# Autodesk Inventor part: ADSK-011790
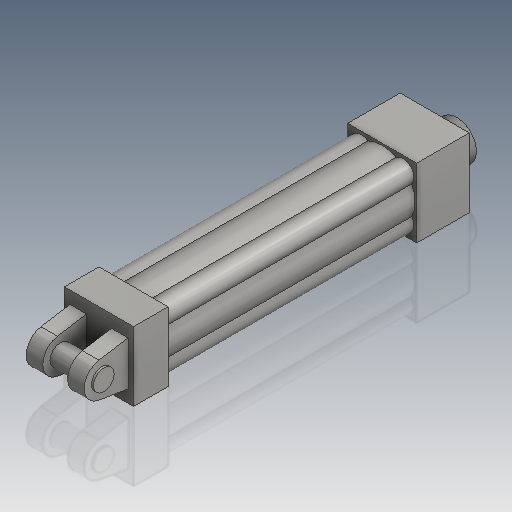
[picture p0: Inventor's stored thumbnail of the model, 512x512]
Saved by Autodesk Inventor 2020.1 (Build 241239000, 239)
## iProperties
Created: 1999-11
Part Number: ADSK-011790
Material: Aluminum
Document SubType Name: Modeling
Designer: kcovelli
Density: 2.71 g/cm^3
Appearance: Steel
Mass: 572.468 g
Surface Area: 962.774 cm^2
Volume: 211.243 cm^3
Control State: 0
Master: False
Checked Out: False
Shininess: 0.0
Length Units: 11269
Angle Units: 11279
Time Units: 11290
Mass Units: 11283
Length Display Precision: 3
Angle Display Precision: 2
Compacted: True
Dimensions: 50x290,7x50 mm
Mass: 0,572 kg
VLT_Material: Aluminum
Density: 0.0
Volumn: 0.0
Area: 0.0
PropertySet Name: Model Information
Author: kcovelli
Revision Number: -
Title: ADSK-011790
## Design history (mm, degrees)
node "Extrusion1" dims "d0" = 38, "d1" = 0
  sketch "Sketch1"
    geometry: L1 (-25, 25)-(25, 25); L2 (25, 25)-(25, -25); L3 (25, -25)-(-25, -25); L4 (-25, -25)-(-25, 25); 3 further points
    constraints: 8 end point, 2 midpoint, 2 parallel, 1 horizontal, 1 horizontal alignment, 1 perpendicular, 1 vertical alignment
    dimensions: "d3" = 50 distance of L1.end L2.end (= d64); "d64" = 50 distance between parallel lines of L2 L4
node "Extrusion3" dims "d24" = 180, "d25" = 0
  sketch "Sketch5"
    geometry: L1 (-25, -25)-(-25, 25) reference; L2 (25, -25)-(-25, -25) reference; L3 (-15, 15)-(15, 15); L4 (15, 15)-(15, -15); L5 (15, -15)-(-15, -15); L6 (-15, -15)-(-15, 15); C1 r 8 at (-15, 15); C2 r 8 at (15, 15); C3 r 8 at (-15, -15); C4 r 8 at (15, -15); C5 r 23.75 at (0, 0); 5 further points
    constraints: 8 end point, 5 centre point, 4 midpoint, 2 coincident, 2 horizontal alignment, 2 parallel, 2 vertical alignment, 1 horizontal, 1 perpendicular
    dimensions: "d17" = 16 diameter of C1 (= d18); "d18" = 16 diameter of C3; "d23" = 47.5 diameter of C5; "d68" = 30 distance of L3.start L3.end; "d69" = 30 distance of L5.end L3.start (= d68); "d70" = 16 diameter of C2 (= d18); "d71" = 16 diameter of C4 (= d18)
node "Shell1" dims "d26" = 3
node "Extrusion4" dims "d27" = 12.5, "d28" = 0
  sketch "Sketch6"
    geometry: L1 (-25, -25)-(-25, 25) reference; L2 (-25, 25)-(25, 25) reference; L3 (25, 25)-(25, -25) reference; L4 (25, -25)-(-25, -25) reference
node "Extrusion5" dims "d29" = 12.5, "d30" = 0
node "Extrusion6" dims "d37" = 50, "d38" = 0
  sketch "Sketch8"
    geometry: L1 (-21, 16)-(-9, 16); L2 (-9, 16)-(-9, -16); L3 (-9, -16)-(-21, -16); L4 (-21, -16)-(-21, 16); L5 (-25, 25)-(25, 25) reference; L6 (25, -25)-(-25, -25) reference; L7 (0, 25)-(0, -25); 2 further points
    constraints: 10 end point, 4 midpoint, 2 parallel, 1 horizontal, 1 horizontal alignment, 1 perpendicular
    dimensions: "d36" = 12 distance of L2.end L3.end; "d65" = 32 distance between parallel lines of L1 L3; "d72" = 9 distance between parallel lines of L7 L2
workplane "Work Plane1"
workplane "Arbeitsebene5"
node "Extrusion7" dims "d43" = 47.625, "d44" = 0
  sketch "Sketch10"
    geometry: L1 (25, 9)-(25, 41) reference; L2 (25, 41)-(75, 41) reference; L3 (25, 9)-(75, 9) reference; L4 (75, 9)-(75, 41) reference; C1 r 7.5 at (44, 25); 1 further point
    constraints: 1 centre point, 1 horizontal alignment, 1 midpoint
    dimensions: "d41" = 19 distance from line of C1.centre L1; "d73" = 15 diameter of C1
node "Extrusion8" dims "d46" = 16, "d47" = 0
node "Extrusion9" dims "d52" = 16, "d53" = 0
  sketch "Sketch13"
    geometry: C1 r 14.25 at (0, 0); 1 further point
    constraints: 1 centre point, 1 coincident
    dimensions: "d51" = 28.5 diameter of C1
node "Extrusion10" dims "d55" = 76.2, "d56" = 0
  sketch "Sketch14"
    geometry: C1 r 14.25 at (0, 0) reference; C2 r 8 at (0, 0)
    constraints: 1 centre point, 1 coincident
    dimensions: "d54" = 16 diameter of C2
node "Mirror3"
node "Solide1"
node "Corps solides"
node "Corps surfaciques"
sketch "Sketch7"
  geometry: L1 (-25, -25)-(-25, 25) reference; L2 (25, -25)-(-25, -25) reference; L3 (25, 25)-(25, -25) reference; L4 (-25, 25)-(25, 25) reference
sketch "Sketch11"
  geometry: L1 (0, 0)-(0, 32) reference; L2 (-50, 32)-(0, 32) reference; L3 (-50, 0)-(0, 0) reference; L4 (-28.936, 3.469)-(-50, 0); L5 (-28.936, 28.531)-(-50, 32); C1 r 7.5 at (-31, 16) reference; A1 r 12.7 centre (-31, 16) between (-28.936, 3.469) and (-28.936, 28.531)
  constraints: 4 end point, 2 point on circle, 2 tangent, 1 centre point, 1 coincident
  dimensions: "d45" = 12.7 radius of A1
other parameters: "d74" = -2.5, "d75" = -2.5
